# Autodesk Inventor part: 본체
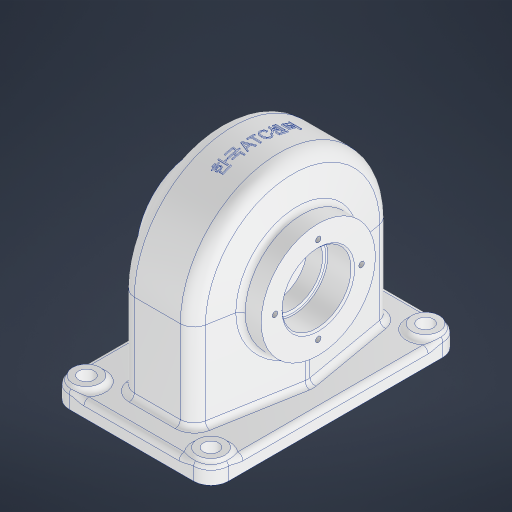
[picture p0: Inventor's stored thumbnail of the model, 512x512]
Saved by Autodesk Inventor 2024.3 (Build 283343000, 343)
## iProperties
Created: 2025-05
Part Number: 본체
Material: 알루미늄 6061
Document SubType Name: Modeling
Designer: user
Density: 2.7 g/cm^3
Appearance: 알루미늄 - 평지
Mass: 741.431 g
Surface Area: 912.594 cm^2
Volume: 274.604 cm^3
Author: user
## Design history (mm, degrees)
sketch "스케치1"
  geometry: L1 (0, 30.051)-(0, -30.051); L2 (0, 30.051)-(57, 20); L3 (57, 20)-(57, -20); L4 (57, -20)-(0, -30.051); 2 further points
  constraints: 8 end point, 2 vertical, 1 coincident, 1 equal length, 1 midpoint
  dimensions: "d4" = 20 deg angle of L2 L4; "d5" = 40 distance of L2.end L3.end; "d6" = 114 diameter of L3 L1
revolve "회전1" sketch "스케치1" stored, may be unused: angle "d0" = 180 deg
sketch "스케치2"
  geometry: L1 (0, 40)-(57, 50.051) reference; L2 (0, 0)-(0, 40) reference; L3 (57, -10.051)-(0, 0) reference; L4 (57, -10.051)-(114, 0) reference; L5 (114, 0)-(114, 40) reference; L6 (114, 40)-(57, 50.051) reference; 1 further point
extrude "돌출1" join sketch "스케치2" distance "d1" = 60; taper "d2" = 0 deg
fillet "모깎기1" dims "d7" = 8
feature "쉘1" dims "d3" = 5
sketch "스케치3"
  geometry: L1 (-15, -26)-(129, -26); L2 (129, -26)-(129, 66); L3 (129, 66)-(-15, 66); L4 (-15, 66)-(-15, -26); L5 (-15, -26)-(129, 66); L6 (129, -26)-(-15, 66); 1 further point
  constraints: 12 end point, 2 midpoint, 2 parallel, 1 horizontal, 1 perpendicular
  dimensions: "d8" = 144 distance of L2.end L3.end; "d9" = 92 distance between parallel lines of L3 L1
extrude "돌출2" join sketch "스케치3" distance "d10" = 9; taper "d11" = 0 deg
fillet "모깎기2" dims "d12" = 10
sketch "스케치4"
  geometry: C1 r 8 at (-119, -16); C2 r 8 at (5, -16); A1 r 10 centre (-119, -16) between (-129, -16) and (-119, -26) reference; A2 r 10 centre (5, -16) between (5, -26) and (15, -16) reference; 3 further points
  constraints: 2 centre point, 2 coincident
  dimensions: "d13" = 16 diameter of C1; "d14" = 16 diameter of C2
extrude "돌출3" join sketch "스케치4" distance "d15" = 3; taper "d16" = 0 deg
sketch "스케치5"
  geometry: C1 r 8 at (0, 0) reference; 2 further points
  constraints: 1 coincident
hole "구멍1" sketch "스케치5" at (0, 0) diameter "d17" = 9; stored, may be unused: countersink angle "d21" = 90 deg, drill point angle "d23" = 118 deg; dims "d18" = 6, "d19" = 4, "d20" = 2, "d22" = 8
sketch "스케치6"
  geometry: C1 r 8 at (0, 0) reference; 2 further points
  constraints: 1 coincident
hole "구멍2" sketch "스케치6" at (0, 0) diameter "d24" = 9; stored, may be unused: countersink angle "d28" = 90 deg, drill point angle "d30" = 118 deg; dims "d25" = 6, "d26" = 4, "d27" = 2, "d29" = 8
node "작업 평면1"
sketch "스케치8"
  geometry: C1 r 24 at (0, 0); 1 further point
  constraints: 1 centre point, 1 coincident
  dimensions: "d32" = 48 diameter of C1
extrude "돌출4" join sketch "스케치8" stored distance "d33" = 3; taper "d34" = 0 deg
node "작업 평면2"
sketch "스케치9"
  geometry: C1 r 33 at (0, 0); 1 further point
  constraints: 1 centre point, 1 coincident
  dimensions: "d36" = 66 diameter of C1
extrude "돌출5" join sketch "스케치9" stored distance "d37" = 10; taper "d38" = 0 deg
sketch "스케치10"
  geometry: C1 r 33 at (0, 0) reference; 2 further points
  constraints: 1 coincident
hole "구멍3" sketch "스케치10" at (0, 0) diameter "d39" = 35; stored, may be unused: countersink angle "d43" = 90 deg, drill point angle "d45" = 0 deg; dims "d40" = 6, "d41" = 40, "d42" = 15, "d44" = 8
sketch "스케치11"
  geometry: L1 (0, 0)-(0, -25); C1 r 33 at (0, 0) reference; 1 further point
  constraints: 2 end point, 1 coincident, 1 vertical
  dimensions: "d46" = 25 distance of L1.start L1.end
hole "구멍4" sketch "스케치11" at (0, -25) diameter "d47" = 3.242; stored, may be unused: countersink angle "d51" = 90 deg, drill point angle "d53" = 118 deg; dims "d48" = 8, "d49" = 40, "d50" = 15, "d52" = 10
fillet "모깎기3" dims "d57" = 3
fillet "모깎기4" dims "d58" = 3
chamfer "모따기1" distance "d59" = 1; stored, may be unused: second distance "d60" = 2, angle "d61" = 45 deg
fillet "모깎기5" dims "d62" = 3
fillet "모깎기6" dims "d63" = 0.6
node "작업 평면4"
sketch "스케치12" dims "d4" = 20 deg, "d5" = 40, "d6" = 114
  geometry: 2 further points
  constraints: 1 coincident, 1 other
feature "엠보싱1" sketch "스케치12" dims "d66" = 0.5, "d67" = 0
sketch "스케치13"
  geometry: L1 (-5, 33.287)-(-5, 6.713) reference; L2 (-56.479, 44.882)-(-7.479, 36.242) reference; L3 (-106.521, 36.242)-(-57.521, 44.882) reference; L4 (-109, 6.713)-(-109, 33.287) reference; L5 (-57.521, -4.882)-(-106.521, 3.758) reference; L6 (-7.479, 3.758)-(-56.479, -4.882) reference; A1 r 3 centre (-8, 6.713) between (-7.479, 3.758) and (-5, 6.713) reference; A2 r 3 centre (-8, 33.287) between (-5, 33.287) and (-7.479, 36.242) reference; A3 r 3 centre (-57, 41.927) between (-56.479, 44.882) and (-57.521, 44.882) reference; A4 r 3 centre (-106, 33.287) between (-106.521, 36.242) and (-109, 33.287) reference; A5 r 3 centre (-106, 6.713) between (-109, 6.713) and (-106.521, 3.758) reference; A6 r 3 centre (-57, -1.927) between (-57.521, -4.882) and (-56.479, -4.882) reference; 1 further point
extrude "돌출6" cut sketch "스케치13" extent not by distance; stored distance "d68" = 0; taper "d69" = 0 deg
fillet "모깎기7" dims "d70" = 3
feature "ˁ耀˃耀˅耀ˇ耀ˉ耀ˋ耀ˍ耀ˏ耀" dims "d0" = 180 deg, "d1" = 60, "d2" = 0, "d3" = 5, "d4" = 20 deg, "d5" = 40, "d6" = 114, "d7" = 8, "d8" = 144, "d9" = 92, "d10" = 9, "d11" = 0, "d12" = 10, "d13" = 16, "d14" = 16, "d15" = 3, "d16" = 0, "d17" = 9, "d18" = 6, "d19" = 4, "d20" = 2, "d21" = 90 deg, "d22" = 8, "d23" = 118 deg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
node "솔리드1"
mirror "미러1"
mirror "미러2"
pattern_circular "원형 패턴1" dims angle "d55" = 360 deg
mirror "미러3"
feature "A9D066F2-1C7D-4E18-AEED-F7BC21143FA4" dims "d17" = 9, "d18" = 6, "d19" = 4, "d20" = 2, "d21" = 90 deg, "d22" = 8, "d23" = 118 deg
